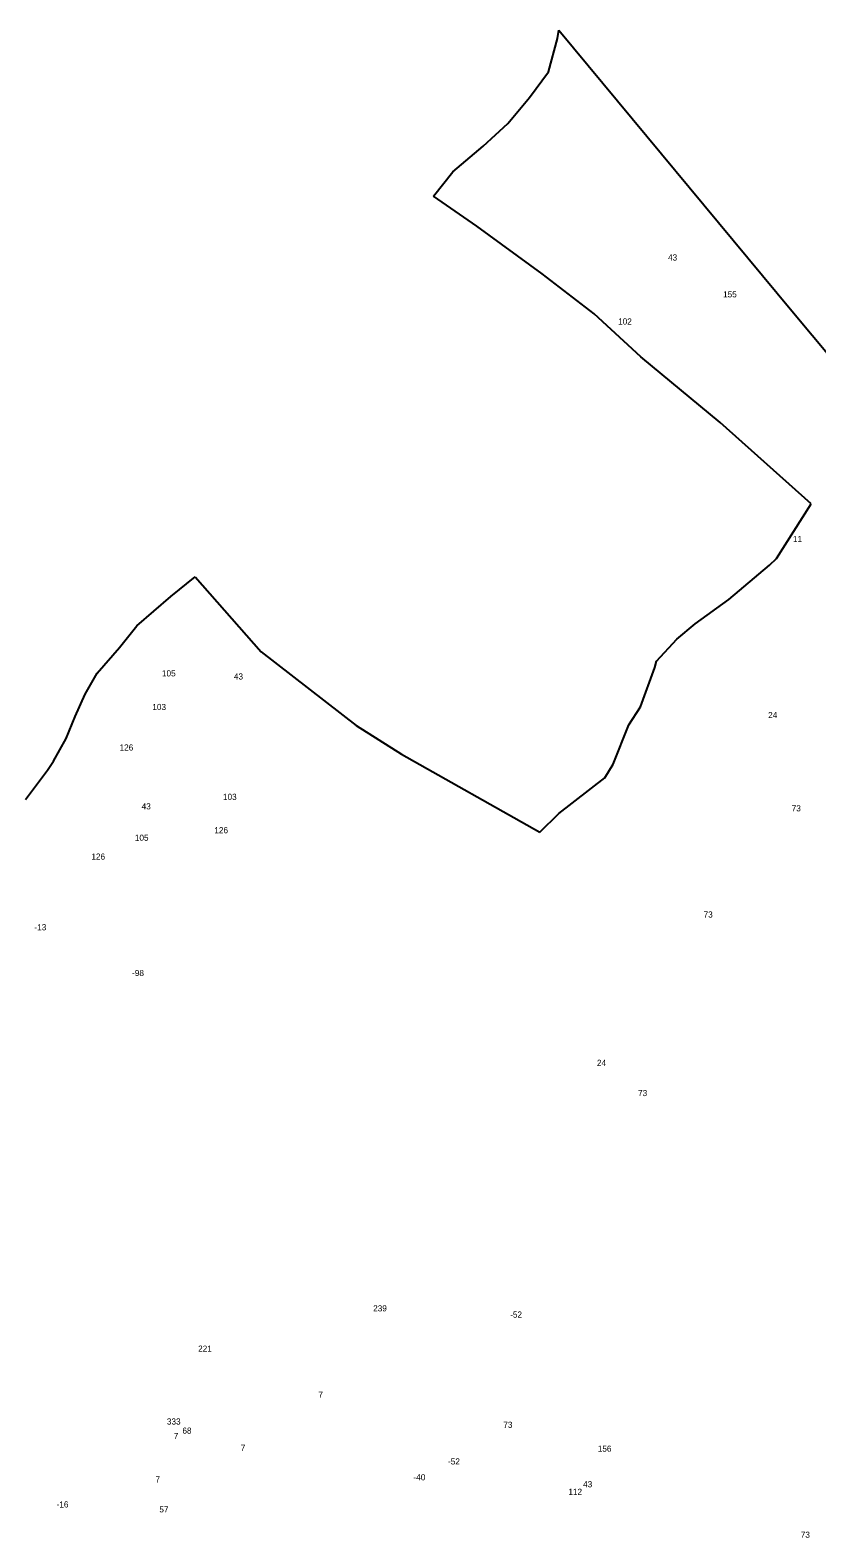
# Model space of a CAD drawing. Extents: x -780116 to -776974, y -980293 to -977147.
# Drawn here: x -779299 to -778487, y -978704 to -977147 of the extents above; entities that cross this region are included whole.
import ezdxf

# ---------------------------------------------------------------- set-up
doc = ezdxf.new("R2010")
doc.units = 0
doc.layers.add('Vrstva 15', color=7, linetype='Continuous')
doc.layers.add('Vrstva 24', color=7, linetype='Continuous')

msp = doc.modelspace()

# ---------------------------------------------------------------- linework, layer by layer
at = {"layer": 'Vrstva 15'}
for p, q in [((-778754.71, -977156.07), (-778753.18, -977147.47)), ((-778753.18, -977147.47), (-778512.79, -977437.25)), ((-778763.95, -977190.43), (-778754.71, -977156.07)), ((-778783.33, -977217.14), (-778763.95, -977190.43)), ((-778805.91, -977243.96), (-778783.33, -977217.14)), ((-778831.41, -977267.23), (-778805.91, -977243.96)), ((-778862.66, -977293.72), (-778831.41, -977267.23)), ((-778882.52, -977318.81), (-778862.66, -977293.72)), ((-778837.85, -977349.69), (-778882.52, -977318.81)), ((-778770.32, -977398.95), (-778837.85, -977349.69)), ((-778716.56, -977440.49), (-778770.32, -977398.95)), ((-778668.64, -977484.7), (-778716.56, -977440.49)), ((-778512.79, -977437.25), (-778438.2, -977526.89)), ((-778586.62, -977552.62), (-778668.64, -977484.7)), ((-778492.66, -977636.57), (-778586.62, -977552.62)), ((-778528.64, -977692.83), (-778492.66, -977636.57)), ((-778535.64, -977699.83), (-778528.64, -977692.83)), ((-779153.72, -977732.13), (-779128.59, -977711.8)), ((-779128.59, -977711.8), (-779060.26, -977789.23)), ((-778577.74, -977735.24), (-778535.64, -977699.83)), ((-779188.9, -977762.66), (-779153.72, -977732.13)), ((-778612.56, -977760.46), (-778577.74, -977735.24)), ((-779206.68, -977785.04), (-779188.9, -977762.66)), ((-778631.57, -977776.38), (-778612.56, -977760.46)), ((-779229.84, -977811.27), (-779206.68, -977785.04)), ((-779060.26, -977789.23), (-778962.35, -977865.31)), ((-778652.26, -977799.04), (-778631.57, -977776.38)), ((-778669.01, -977846.04), (-778654.22, -977805.56)), ((-778654.22, -977805.56), (-778652.26, -977799.04)), ((-779242.01, -977833.06), (-779229.84, -977811.27)), ((-779252.35, -977856.17), (-779242.01, -977833.06)), ((-778680.88, -977864.7), (-778669.01, -977846.04)), ((-779261.82, -977878.98), (-779252.35, -977856.17)), ((-778962.35, -977865.31), (-778915.43, -977894.9)), ((-778697.2, -977905.44), (-778680.88, -977864.7)), ((-779274.86, -977902.15), (-779261.82, -977878.98)), ((-778915.43, -977894.9), (-778772.95, -977975.64)), ((-779303.63, -977941.72), (-779280.83, -977911.55)), ((-779280.83, -977911.55), (-779274.86, -977902.15)), ((-778705.79, -977919.46), (-778697.2, -977905.44)), ((-778753.14, -977956.19), (-778705.79, -977919.46)), ((-778772.95, -977975.64), (-778753.14, -977956.19))]:
    msp.add_line(p, q, dxfattribs=at)

# ---------------------------------------------------------------- texts
at = {"layer": 'Vrstva 24'}
for s, p in [('43', (-778640.505, -977385.334)), ('155', (-778583.681, -977423.384)), ('102', (-778691.995, -977451.424)), ('11', (-778511.541, -977675.994)), ('105', (-779162.805, -977814.744)), ('43', (-779088.535, -977817.924)), ('103', (-779172.725, -977849.464)), ('24', (-778537.155, -977857.824)), ('126', (-779206.551, -977891.254)), ('43', (-779183.775, -977952.054)), ('103', (-779099.825, -977942.224)), ('73', (-778512.819, -977954.074)), ('126', (-779108.741, -977976.704)), ('105', (-779190.795, -977984.524)), ('126', (-779235.651, -978003.934)), ('-13', (-779294.407, -978076.894)), ('73', (-778603.769, -978063.744)), ('-98', (-779193.629, -978124.114)), ('24', (-778713.815, -978216.854)), ('73', (-778671.409, -978248.064)), ('239', (-778944.813, -978470.364)), ('-52', (-778803.439, -978476.794)), ('221', (-779125.481, -978511.974)), ('7', (-779001.382, -978559.564)), ('333', (-779157.703, -978587.184)), ('73', (-778810.479, -978590.614)), ('7', (-779150.612, -978602.134)), ('68', (-779141.695, -978596.634)), ('7', (-779081.532, -978614.374)), ('156', (-778713.001, -978615.284)), ('-52', (-778867.559, -978628.404)), ('7', (-779169.552, -978647.034)), ('-40', (-778903.243, -978644.724)), ('43', (-778728.135, -978651.974)), ('112', (-778743.329, -978659.774)), ('-16', (-779271.517, -978672.834)), ('57', (-779165.5, -978677.904)), ('73', (-778503.499, -978704.074))]:
    msp.add_text(s, height=6.336, dxfattribs=at).set_placement(p)

doc.saveas('drawing.dxf')
